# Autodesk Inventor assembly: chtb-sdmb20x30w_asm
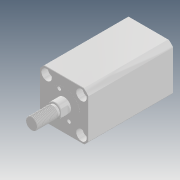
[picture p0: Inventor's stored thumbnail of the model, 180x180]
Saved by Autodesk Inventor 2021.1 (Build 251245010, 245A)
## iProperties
Company: Microsoft
Created: 2018-05
Part Number: chtb-sdmb20x30w_asm
Description: STEP AP214
Document SubType Name: Assembly
Designer: user
Title: chtb-sdmb20x30w_asm.STEP
Author: Windows
Revision Number: ÈÎºÎ
Sending System: SolidWorks 2015
Preprocessor: SwSTEP 2.0
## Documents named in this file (4)
- D:\Vault_2016\Projekty\Clamptek\Hydraulic\CHTB\CHTB-20\Inventor\CHTB-SDMB20x30W\chtb-sdmb20x30w_asm.iam
- D:\Vault_2016\Projekty\Clamptek\Hydraulic\CHTB\CHTB-20\Inventor\CHTB-SDMB20x30W\CHTB-SDMB20X30NBT.ipt
- D:\Vault_2016\Projekty\Clamptek\Hydraulic\CHTB\CHTB-20\Inventor\CHTB-SDMB20x30W\CHTB-SDMB20X30WHSG.ipt
- D:\Vault_2016\Projekty\Clamptek\Hydraulic\CHTB\CHTB-20\Inventor\CHTB-SDMB20x30W\QG_3.ipt
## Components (3 placed, 3 different names)
1. CHTB-SDMB20X30NBT_1
2. CHTB-SDMB20X30WHSG_2
3. QG_3_3
